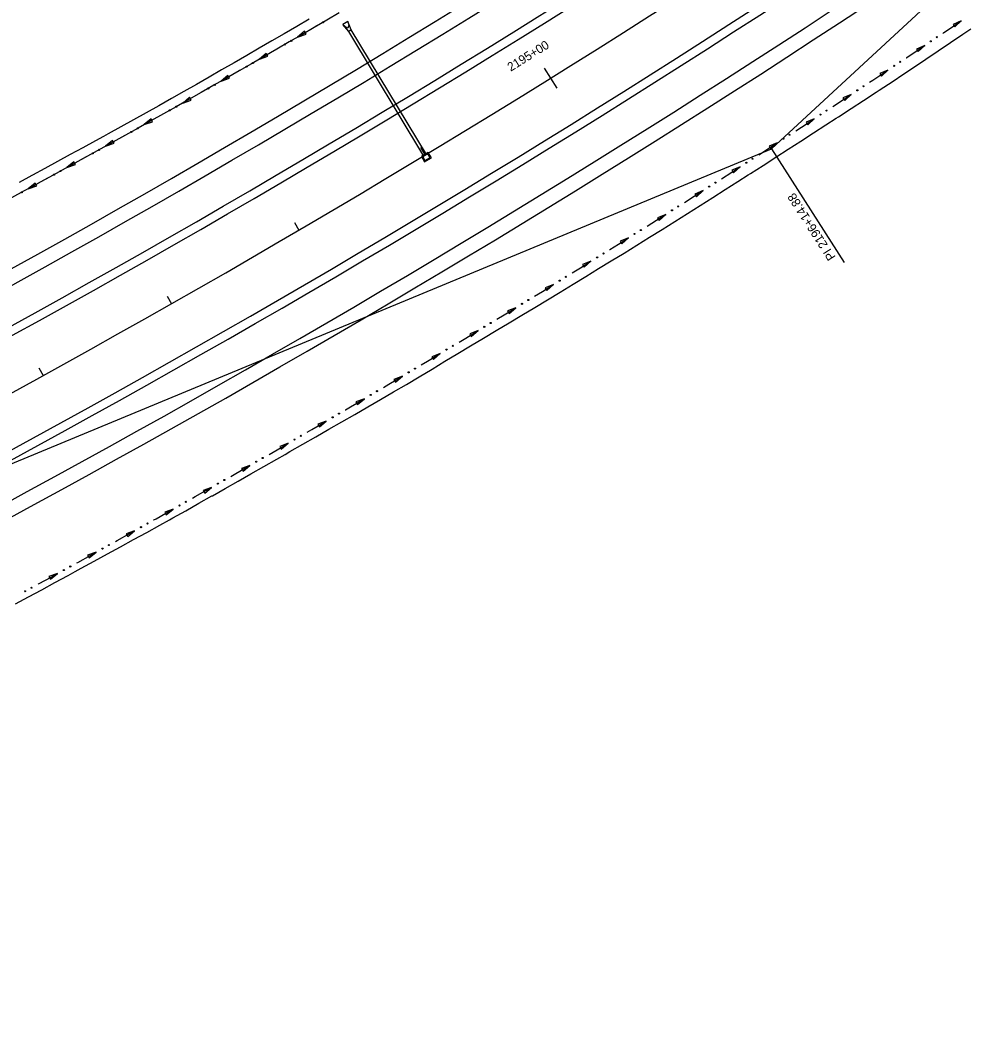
# Model space of a CAD drawing. Extents: x 1611108 to 1749517, y 619561 to 797725.
# Drawn here: x 1724610 to 1725252, y 768957 to 769635 of the extents above; entities that cross this region are included whole.
import ezdxf

# ---------------------------------------------------------------- set-up
doc = ezdxf.new("R2010")
doc.units = 0
for name, color, linetype in [('R_Ditch', 7, 'Continuous'), ('R_Drainage', 7, 'Continuous'), ('R_Horz Alg', 7, 'Continuous'), ('R_Horz Alg Annot', 7, 'Continuous'), ('R_Horz Alg Stationing', 7, 'Continuous'), ('R_Proposed Const Limits', 7, 'Continuous'), ('R_Proposed Road', 7, 'Continuous')]:
    doc.layers.add(name, color=color, linetype=linetype)

msp = doc.modelspace()

# ---------------------------------------------------------------- linework, layer by layer
at = {"layer": 'R_Ditch'}
for p, q in [((1725250.1, 769634.82), (1725244.54, 769632.34)), ((1725245.72, 769630.58), (1725250.1, 769634.82)), ((1724803.35, 769627.64), (1724798.7, 769623.71)), ((1724804.42, 769625.81), (1724803.35, 769627.64)), ((1725244.54, 769632.34), (1725245.72, 769630.58)), ((1724798.7, 769623.71), (1724804.42, 769625.81)), ((1724777.37, 769612.57), (1724772.7, 769608.66)), ((1724778.43, 769610.74), (1724777.37, 769612.57)), ((1725225.19, 769618.03), (1725219.62, 769615.56)), ((1725219.62, 769615.56), (1725220.8, 769613.8)), ((1725220.8, 769613.8), (1725225.19, 769618.03)), ((1724772.7, 769608.66), (1724778.43, 769610.74)), ((1725200.23, 769601.32), (1725194.65, 769598.88)), ((1725195.82, 769597.12), (1725200.23, 769601.32)), ((1724751.33, 769597.61), (1724746.64, 769593.72)), ((1724746.64, 769593.72), (1724752.38, 769595.78)), ((1724752.38, 769595.78), (1724751.33, 769597.61)), ((1725194.65, 769598.88), (1725195.82, 769597.12)), ((1724725.22, 769582.76), (1724720.52, 769578.88)), ((1724720.52, 769578.88), (1724726.27, 769580.92)), ((1724726.27, 769580.92), (1724725.22, 769582.76)), ((1725175.2, 769584.72), (1725169.61, 769582.3)), ((1725169.61, 769582.3), (1725170.77, 769580.53)), ((1725170.77, 769580.53), (1725175.2, 769584.72)), ((1724699.06, 769568.01), (1724694.34, 769564.15)), ((1724694.34, 769564.15), (1724700.1, 769566.16)), ((1724700.1, 769566.16), (1724699.06, 769568.01)), ((1725150.1, 769568.21), (1725144.5, 769565.81)), ((1725144.5, 769565.81), (1725145.66, 769564.04)), ((1725145.66, 769564.04), (1725150.1, 769568.21)), ((1724672.84, 769553.36), (1724668.11, 769549.52)), ((1724668.11, 769549.52), (1724673.87, 769551.51)), ((1724673.87, 769551.51), (1724672.84, 769553.36)), ((1725124.94, 769551.8), (1725119.33, 769549.42)), ((1725120.49, 769547.65), (1725124.94, 769551.8)), ((1725119.33, 769549.42), (1725120.49, 769547.65)), ((1724646.56, 769538.82), (1724641.82, 769535)), ((1724647.58, 769536.96), (1724646.56, 769538.82)), ((1724641.82, 769535), (1724647.58, 769536.96)), ((1725099.72, 769535.49), (1725094.1, 769533.13)), ((1725094.1, 769533.13), (1725095.25, 769531.35)), ((1725095.25, 769531.35), (1725099.72, 769535.49)), ((1724620.23, 769524.38), (1724615.46, 769520.58)), ((1724621.24, 769522.52), (1724620.23, 769524.38)), ((1724615.46, 769520.58), (1724621.24, 769522.52)), ((1725074.43, 769519.27), (1725068.81, 769516.94)), ((1725069.95, 769515.15), (1725074.43, 769519.27)), ((1725068.81, 769516.94), (1725069.95, 769515.15)), ((1725049.09, 769503.16), (1725043.45, 769500.84)), ((1725043.45, 769500.84), (1725044.58, 769499.05)), ((1725044.58, 769499.05), (1725049.09, 769503.16)), ((1725023.68, 769487.14), (1725018.03, 769484.85)), ((1725018.03, 769484.85), (1725019.16, 769483.05)), ((1725019.16, 769483.05), (1725023.68, 769487.14)), ((1724998.21, 769471.22), (1724992.55, 769468.95)), ((1724993.67, 769467.15), (1724998.21, 769471.22)), ((1724992.55, 769468.95), (1724993.67, 769467.15)), ((1724972.67, 769455.39), (1724967.01, 769453.15)), ((1724967.01, 769453.15), (1724968.12, 769451.35)), ((1724968.12, 769451.35), (1724972.67, 769455.39)), ((1724947.08, 769439.67), (1724941.41, 769437.45)), ((1724941.41, 769437.45), (1724942.51, 769435.64)), ((1724942.51, 769435.64), (1724947.08, 769439.67)), ((1724921.42, 769424.05), (1724915.74, 769421.84)), ((1724916.84, 769420.03), (1724921.42, 769424.05)), ((1724915.74, 769421.84), (1724916.84, 769420.03)), ((1724895.71, 769408.52), (1724890.02, 769406.34)), ((1724890.02, 769406.34), (1724891.11, 769404.53)), ((1724891.11, 769404.53), (1724895.71, 769408.52)), ((1724869.93, 769393.1), (1724864.24, 769390.94)), ((1724864.24, 769390.94), (1724865.32, 769389.12)), ((1724865.32, 769389.12), (1724869.93, 769393.1)), ((1724844.1, 769377.77), (1724838.39, 769375.64)), ((1724838.39, 769375.64), (1724839.47, 769373.81)), ((1724839.47, 769373.81), (1724844.1, 769377.77)), ((1724818.2, 769362.55), (1724812.49, 769360.44)), ((1724813.56, 769358.61), (1724818.2, 769362.55)), ((1724812.49, 769360.44), (1724813.56, 769358.61)), ((1724792.25, 769347.42), (1724786.53, 769345.33)), ((1724786.53, 769345.33), (1724787.59, 769343.5)), ((1724787.59, 769343.5), (1724792.25, 769347.42)), ((1724766.24, 769332.4), (1724760.51, 769330.33)), ((1724760.51, 769330.33), (1724761.56, 769328.5)), ((1724761.56, 769328.5), (1724766.24, 769332.4)), ((1724740.17, 769317.48), (1724734.43, 769315.43)), ((1724734.43, 769315.43), (1724735.48, 769313.59)), ((1724735.48, 769313.59), (1724740.17, 769317.48)), ((1724714.04, 769302.66), (1724708.3, 769300.63)), ((1724708.3, 769300.63), (1724709.34, 769298.78)), ((1724709.34, 769298.78), (1724714.04, 769302.66)), ((1724687.86, 769287.94), (1724682.11, 769285.93)), ((1724683.14, 769284.08), (1724687.86, 769287.94)), ((1724682.11, 769285.93), (1724683.14, 769284.08)), ((1724661.62, 769273.32), (1724655.86, 769271.33)), ((1724655.86, 769271.33), (1724656.89, 769269.48)), ((1724656.89, 769269.48), (1724661.62, 769273.32)), ((1724635.32, 769258.8), (1724629.56, 769256.84)), ((1724629.56, 769256.84), (1724630.58, 769254.98)), ((1724630.58, 769254.98), (1724635.32, 769258.8))]:
    msp.add_line(p, q, dxfattribs=at)
for points in [[(1724827.03, 769640.26), (1724818.53, 769635.28), (1724810.02, 769630.3), (1724801.51, 769625.34), (1724792.99, 769620.39), (1724784.47, 769615.45), (1724775.94, 769610.53), (1724767.4, 769605.61), (1724758.85, 769600.71), (1724750.3, 769595.81), (1724741.75, 769590.93), (1724733.19, 769586.06), (1724724.62, 769581.2), (1724716.04, 769576.35), (1724707.46, 769571.51), (1724698.87, 769566.69), (1724690.28, 769561.87), (1724681.68, 769557.07), (1724673.07, 769552.28), (1724669.84, 769550.48), (1724664.46, 769547.5), (1724655.84, 769542.73), (1724647.22, 769537.97), (1724638.59, 769533.22), (1724629.95, 769528.49), (1724621.62, 769523.93), (1724621.31, 769523.77), (1724612.66, 769519.05), (1724604.01, 769514.35)], [(1725237.67, 769626.42), (1725238.31, 769626.86), (1725246.73, 769632.54), (1725250.1, 769634.82)], [(1724811.66, 769631.26), (1724810.02, 769630.3), (1724801.51, 769625.34), (1724798.7, 769623.71)], [(1724811.69, 769631.28), (1724811.66, 769631.26)], [(1725237.64, 769626.4), (1725237.67, 769626.42)], [(1724785.69, 769616.16), (1724784.47, 769615.45), (1724775.94, 769610.53), (1724772.7, 769608.66)], [(1724785.72, 769616.18), (1724785.69, 769616.16)], [(1725212.74, 769609.67), (1725213.02, 769609.87), (1725221.46, 769615.52), (1725225.19, 769618.03)], [(1725212.7, 769609.65), (1725212.74, 769609.67)], [(1724759.66, 769601.17), (1724758.85, 769600.71), (1724750.3, 769595.81), (1724746.64, 769593.72)], [(1724759.69, 769601.19), (1724759.66, 769601.17)], [(1725187.74, 769593.02), (1725189.85, 769594.42), (1725196.13, 769598.59), (1725200.23, 769601.32)], [(1725187.71, 769593), (1725187.74, 769593.02)], [(1724733.57, 769586.28), (1724733.19, 769586.06), (1724724.62, 769581.2), (1724720.52, 769578.88)], [(1724733.61, 769586.3), (1724733.57, 769586.28)], [(1725162.67, 769576.46), (1725170.73, 769581.77), (1725175.2, 769584.72)], [(1725162.64, 769576.44), (1725162.67, 769576.46)], [(1724707.42, 769571.49), (1724698.87, 769566.69), (1724694.34, 769564.15)], [(1724707.46, 769571.51), (1724707.43, 769571.49)], [(1725137.55, 769560), (1725145.26, 769565.04), (1725150.1, 769568.21)], [(1725137.51, 769559.98), (1725137.55, 769560)], [(1724681.22, 769556.81), (1724673.07, 769552.28), (1724669.84, 769550.48), (1724668.11, 769549.52)], [(1724681.25, 769556.83), (1724681.22, 769556.81)], [(1725112.36, 769543.64), (1725119.73, 769548.41), (1725124.94, 769551.8)], [(1724654.95, 769542.24), (1724647.22, 769537.97), (1724641.82, 769535)], [(1724654.99, 769542.26), (1724654.95, 769542.24)], [(1725112.32, 769543.62), (1725112.36, 769543.64)], [(1725087.1, 769527.38), (1725094.13, 769531.89), (1725099.72, 769535.49)], [(1724628.63, 769527.77), (1724621.62, 769523.93), (1724621.31, 769523.77), (1724615.46, 769520.58)], [(1724628.66, 769527.79), (1724628.63, 769527.77)], [(1725087.07, 769527.36), (1725087.1, 769527.38)], [(1725061.79, 769511.21), (1725068.46, 769515.46), (1725074.43, 769519.27)], [(1725061.75, 769511.19), (1725061.78, 769511.21)], [(1725036.41, 769495.14), (1725042.73, 769499.14), (1725049.09, 769503.16)], [(1725036.37, 769495.12), (1725036.41, 769495.14)], [(1725010.96, 769479.17), (1725016.94, 769482.91), (1725023.68, 769487.14)], [(1725010.93, 769479.15), (1725010.96, 769479.17)], [(1724985.46, 769463.3), (1724991.08, 769466.79), (1724998.21, 769471.22)], [(1724985.43, 769463.28), (1724985.46, 769463.3)], [(1724959.9, 769447.53), (1724965.16, 769450.76), (1724972.67, 769455.39)], [(1724959.87, 769447.51), (1724959.9, 769447.53)], [(1724934.27, 769431.86), (1724939.18, 769434.84), (1724947.08, 769439.67)], [(1724934.24, 769431.84), (1724934.27, 769431.86)], [(1724908.59, 769416.28), (1724913.13, 769419.02), (1724921.42, 769424.05)], [(1724908.56, 769416.26), (1724908.59, 769416.28)], [(1724882.84, 769400.81), (1724887.02, 769403.31), (1724895.71, 769408.52)], [(1724882.81, 769400.79), (1724882.84, 769400.81)], [(1724857.04, 769385.43), (1724860.84, 769387.69), (1724869.57, 769392.89), (1724869.93, 769393.1)], [(1724857.01, 769385.42), (1724857.04, 769385.43)], [(1724831.17, 769370.16), (1724834.61, 769372.18), (1724843.36, 769377.34), (1724844.1, 769377.77)], [(1724831.14, 769370.14), (1724831.17, 769370.16)], [(1724805.25, 769354.99), (1724808.31, 769356.77), (1724817.09, 769361.9), (1724818.2, 769362.55)], [(1724805.22, 769354.97), (1724805.25, 769354.99)], [(1724779.27, 769339.91), (1724781.96, 769341.46), (1724787.45, 769344.64), (1724790.75, 769346.55), (1724792.25, 769347.43)], [(1724779.24, 769339.89), (1724779.27, 769339.91)], [(1724753.23, 769324.94), (1724755.54, 769326.26), (1724764.35, 769331.32), (1724766.24, 769332.4)], [(1724753.2, 769324.92), (1724753.23, 769324.94)], [(1724727.13, 769310.06), (1724729.06, 769311.16), (1724737.9, 769316.18), (1724738.21, 769316.36), (1724740.17, 769317.48)], [(1724727.1, 769310.05), (1724727.13, 769310.06)], [(1724700.98, 769295.29), (1724702.53, 769296.16), (1724709.06, 769299.84), (1724711.38, 769301.15), (1724714.04, 769302.66)], [(1724700.94, 769295.27), (1724700.98, 769295.29)], [(1724674.76, 769280.62), (1724675.93, 769281.27), (1724684.8, 769286.22), (1724687.86, 769287.94)], [(1724674.73, 769280.6), (1724674.76, 769280.62)], [(1724648.5, 769266.05), (1724649.28, 769266.48), (1724658.17, 769271.4), (1724661.62, 769273.32)], [(1724648.46, 769266.04), (1724648.5, 769266.05)], [(1724622.17, 769251.59), (1724622.56, 769251.8), (1724631.47, 769256.68), (1724635.32, 769258.8)], [(1724622.14, 769251.57), (1724622.17, 769251.59)]]:
    msp.add_lwpolyline(points, dxfattribs=at)
for centre in [(1724816.01, 769633.76), (1724794.39, 769621.16), (1725229.33, 769620.85), (1725233.48, 769623.65), (1724790.05, 769618.65), (1724768.38, 769606.13), (1725208.54, 769606.91), (1724764.03, 769603.64), (1725204.37, 769604.13), (1724737.96, 769588.73), (1724742.31, 769591.21), (1725179.35, 769587.51), (1725183.53, 769590.28), (1724711.82, 769573.93), (1724716.18, 769576.39), (1725158.46, 769573.74), (1725154.27, 769570.99), (1724685.62, 769559.23), (1724690, 769561.67), (1725129.12, 769554.56), (1725133.32, 769557.29), (1724659.37, 769544.64), (1724663.75, 769547.06), (1725103.91, 769538.23), (1725108.12, 769540.95), (1724637.45, 769532.56), (1724633.05, 769530.15), (1725082.85, 769524.7), (1724611.09, 769518.16), (1725078.63, 769522), (1725053.3, 769505.87), (1725057.53, 769508.55), (1725032.14, 769492.5), (1725027.9, 769489.83), (1725006.69, 769476.54), (1725002.44, 769473.89), (1724976.91, 769458.06), (1724981.17, 769460.69), (1724955.6, 769444.93), (1724951.33, 769442.32), (1724929.97, 769429.28), (1724925.68, 769426.68), (1724899.98, 769411.14), (1724904.27, 769413.72), (1724874.21, 769395.69), (1724878.52, 769398.26), (1724852.7, 769382.9), (1724848.39, 769380.35), (1724822.5, 769365.11), (1724826.83, 769367.65), (1724796.56, 769349.97), (1724800.89, 769352.49), (1724770.56, 769334.93), (1724774.9, 769337.43), (1724748.85, 769322.48), (1724744.5, 769319.99), (1724722.74, 769307.62), (1724718.38, 769305.15), (1724692.21, 769290.41), (1724696.58, 769292.87), (1724665.98, 769275.78), (1724670.36, 769278.21), (1724639.69, 769261.24), (1724644.08, 769263.66), (1724613.35, 769246.81), (1724617.75, 769249.21)]:
    msp.add_circle(centre, 0.375, dxfattribs=at)
at = {"layer": 'R_Drainage'}
for p, q in [((1724832.91, 769634.39), (1724829.48, 769632.33)), ((1724835.21, 769628.64), (1724832.91, 769634.39)), ((1724832.91, 769634.39), (1724833.59, 769631.54)), ((1724833.5, 769627.6), (1724829.48, 769632.33)), ((1724829.48, 769632.33), (1724831.69, 769630.39)), ((1724835.21, 769628.64), (1724833.5, 769627.6)), ((1724884.63, 769542.82), (1724833.5, 769627.6)), ((1724886.34, 769543.86), (1724835.21, 769628.64))]:
    msp.add_line(p, q, dxfattribs=at)
for points in [[(1724882.85, 769542.53), (1724885.09, 769538.82), (1724889.66, 769541.58), (1724887.42, 769545.29)], [(1724883.77, 769542.31), (1724885.32, 769539.74), (1724888.74, 769541.81), (1724887.19, 769544.37)]]:
    msp.add_lwpolyline(points, close=True, dxfattribs=at)
msp.add_arc((1724832.46, 769631.26), 1.17, 228.62301, 13.56316, dxfattribs=at)
at = {"layer": 'R_Horz Alg'}
msp.add_arc((1720937.13, 776083.5), 7639.44, 292.5, 312.75, dxfattribs=at)
at = {"layer": 'R_Horz Alg Annot'}
for points in [[(1725121, 769547.65), (1726122.78, 770473.69)], [(1723860.62, 769025.58), (1725121, 769547.65)], [(1725121, 769547.65), (1725170.5, 769470.32)]]:
    msp.add_lwpolyline(points, dxfattribs=at)
at = {"layer": 'R_Horz Alg Stationing'}
for points in [[(1724966.49, 769602.53), (1724974.94, 769588.94)], [(1724882.35, 769548.63), (1724885.45, 769543.49)], [(1724796.47, 769497.54), (1724799.5, 769492.37)], [(1724709.93, 769447.59), (1724712.9, 769442.38)], [(1724622.75, 769398.77), (1724625.65, 769393.52)]]:
    msp.add_lwpolyline(points, dxfattribs=at)
at = {"layer": 'R_Proposed Const Limits'}
for points in [[(1724806.66, 769635.91), (1724798.15, 769630.96), (1724789.63, 769626.03), (1724781.11, 769621.1), (1724772.57, 769616.19), (1724764.07, 769611.24), (1724755.56, 769606.29), (1724747.04, 769601.36), (1724738.52, 769596.44), (1724729.98, 769591.54), (1724721.42, 769586.69), (1724712.85, 769581.85), (1724704.27, 769577.03), (1724695.66, 769572.25), (1724687.04, 769567.49), (1724678.44, 769562.72), (1724669.83, 769557.94), (1724666.6, 769556.15), (1724661.22, 769553.19), (1724652.58, 769548.46), (1724643.94, 769543.75), (1724635.31, 769539.03), (1724626.68, 769534.31), (1724618.35, 769529.76), (1724618.04, 769529.59), (1724609.4, 769524.88)], [(1724606.76, 769238.26), (1724615.72, 769243.07), (1724624.67, 769247.89), (1724633.62, 769252.72), (1724642.56, 769257.56), (1724647.35, 769260.19), (1724651.48, 769262.43), (1724660.42, 769267.29), (1724669.34, 769272.16), (1724678.26, 769277.04), (1724687.17, 769281.93), (1724696.08, 769286.83), (1724704.98, 769291.75), (1724711.54, 769295.39), (1724713.87, 769296.68), (1724722.75, 769301.62), (1724731.6, 769306.64), (1724740.45, 769311.63), (1724740.77, 769311.81), (1724749.32, 769316.61), (1724758.16, 769321.63), (1724766.99, 769326.66), (1724775.82, 769331.71), (1724784.65, 769336.75), (1724790.16, 769339.89), (1724793.48, 769341.79), (1724802.3, 769346.84), (1724811.11, 769351.91), (1724819.92, 769356.99), (1724828.74, 769362.05), (1724837.56, 769367.09), (1724846.37, 769372.17), (1724855.16, 769377.28), (1724863.95, 769382.4), (1724872.73, 769387.53), (1724881.46, 769392.73), (1724890.18, 769397.96), (1724898.89, 769403.2), (1724907.6, 769408.45), (1724916.33, 769413.65), (1724925.07, 769418.84), (1724933.81, 769424.05), (1724942.53, 769429.26), (1724951.25, 769434.49), (1724959.94, 769439.77), (1724968.63, 769445.04), (1724977.32, 769450.33), (1724986, 769455.62), (1724994.67, 769460.93), (1725003.35, 769466.21), (1725012.03, 769471.51), (1725020.7, 769476.82), (1725029.36, 769482.15), (1725037.99, 769487.53), (1725046.6, 769492.94), (1725055.23, 769498.32), (1725063.82, 769503.74), (1725072.42, 769509.17), (1725081, 769514.62), (1725089.56, 769520.1), (1725098.14, 769525.56), (1725105.08, 769529.94), (1725106.74, 769530.99), (1725115.31, 769536.45), (1725123.87, 769541.94), (1725132.41, 769547.45), (1725140.95, 769552.97), (1725149.49, 769558.49), (1725158.03, 769564), (1725165.08, 769568.55), (1725166.57, 769569.52), (1725175.1, 769575.06), (1725183.61, 769580.61), (1725192.12, 769586.17), (1725194.32, 769587.6), (1725200.62, 769591.76), (1725205.12, 769594.74), (1725209.08, 769597.4), (1725217.51, 769603.07), (1725225.94, 769608.75), (1725234.37, 769614.44), (1725242.78, 769620.14), (1725251.23, 769625.8), (1725256.51, 769629.28)]]:
    msp.add_lwpolyline(points, dxfattribs=at)
at = {"layer": 'R_Proposed Road'}
for radius in [7565.44, 7575.44, 7599.44, 7605.44, 7673.44, 7679.44, 7703.44, 7713.44]:
    msp.add_arc((1720937.13, 776083.5), radius, 292.5, 312.75, dxfattribs=at)

# ---------------------------------------------------------------- texts
at = {"layer": 'R_Horz Alg Annot'}
msp.add_text('PI 2196+14.88', height=6, rotation=122.625, dxfattribs=at).set_placement((1725164.83, 769474.13))
at = {"layer": 'R_Horz Alg Stationing'}
msp.add_text('2195+00', height=6, rotation=31.87011, dxfattribs=at).set_placement((1724943.68, 769600.12))

doc.saveas('drawing.dxf')
